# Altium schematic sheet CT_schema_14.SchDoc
size 278 x 170 mm
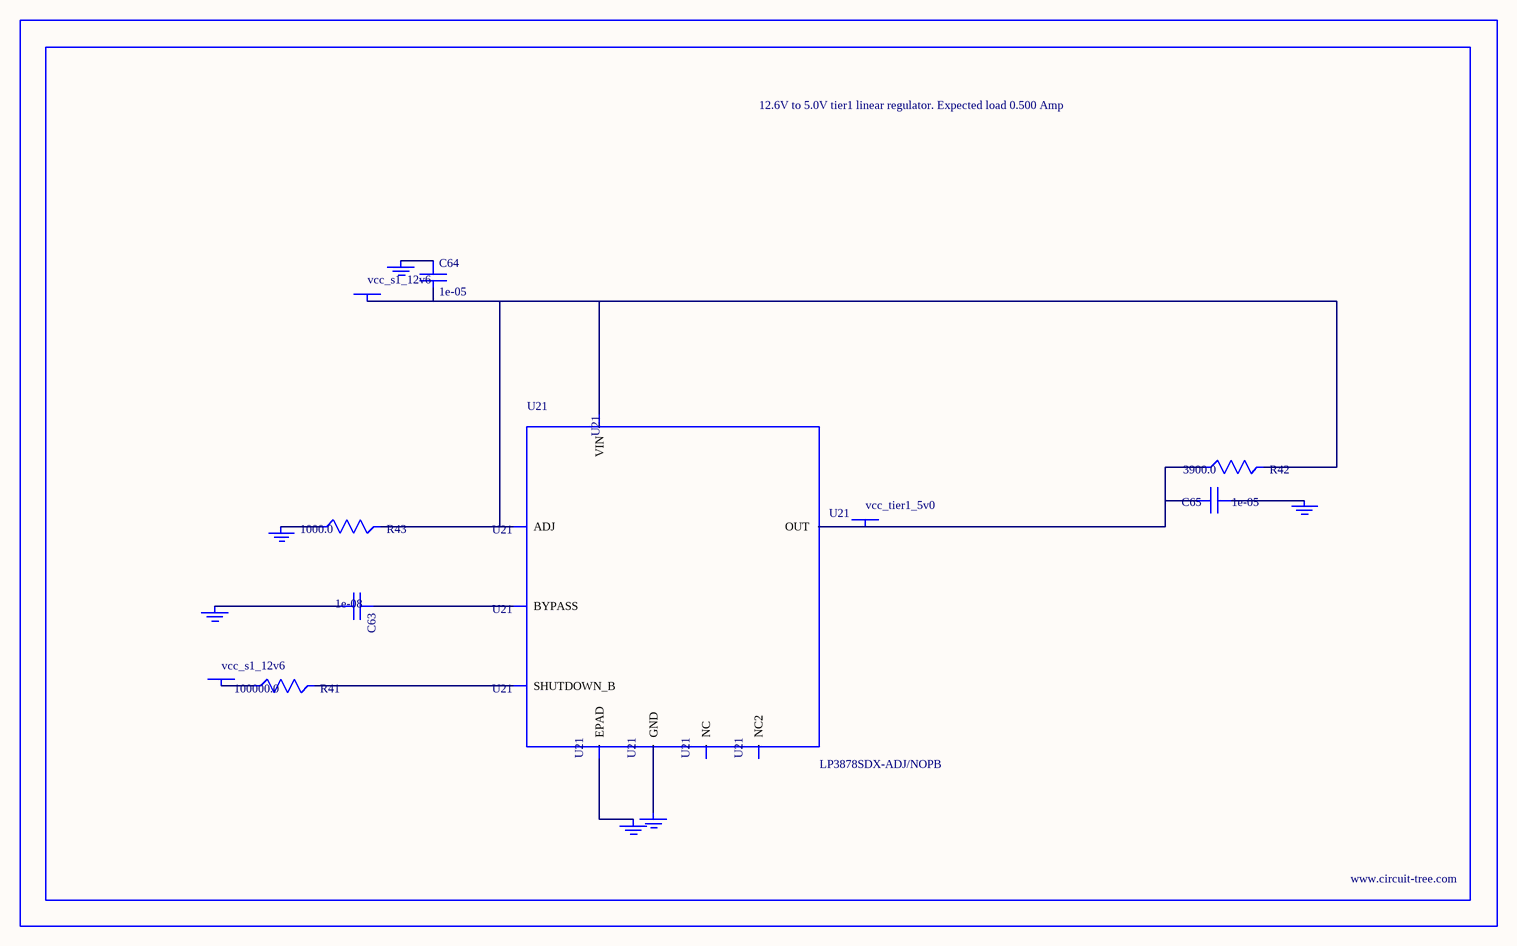
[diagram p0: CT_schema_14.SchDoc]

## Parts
BORDER13  (no value)
C63  1e-08  [C0402]
C64  1e-05  [C1210]
C65  1e-05  [C1210]
GND_INSTANCE_13_0  (no value)
GND_INSTANCE_13_1  (no value)
GND_INSTANCE_13_2  (no value)
GND_INSTANCE_13_3  (no value)
GND_INSTANCE_13_4  (no value)
GND_INSTANCE_13_5  (no value)
POWER_INSTANCE_13_0  vcc_s1_12v6
POWER_INSTANCE_13_1  vcc_s1_12v6
POWER_INSTANCE_13_2  vcc_tier1_5v0
R41  100000.0  [R0603]
R42  3900.0  [R0603]
R43  1000.0  [R0603]
U21  LP3878SDX-ADJ/NOPB  [WSON-8]

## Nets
NetC63_1: C63.1 U21.1(BYPASS)
NetC63_2: C63.2 GND_INSTANCE_13_0.0(GND)
NetC64_1: C64.1 GND_INSTANCE_13_1.0(GND)
NetC64_2: C64.2 POWER_INSTANCE_13_0.0(PWR) R42.2 R43.2 U21.4(VIN) U21.6(ADJ)
NetC65_1: C65.1 GND_INSTANCE_13_2.0(GND)
NetC65_2: C65.2 POWER_INSTANCE_13_2.0(PWR) R42.1 U21.5(OUT)
NetGND_INSTANCE_13_3_0: GND_INSTANCE_13_3.0(GND) R43.1
NetGND_INSTANCE_13_4_0: GND_INSTANCE_13_4.0(GND) U21.PAD(EPAD)
NetGND_INSTANCE_13_5_0: GND_INSTANCE_13_5.0(GND) U21.3(GND)
NetPOWER_INSTANCE_13_1_0: POWER_INSTANCE_13_1.0(PWR) R41.1
NetR41_2: R41.2 U21.8(SHUTDOWN_B)

Not connected (* = marked no-connect by the designer): U21 2(NC) 7(NC2)

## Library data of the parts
BORDER13 = BORDER_PAGE13
C63 = C0402C103K3RAC
C64 = C1210C106K5PACTU
C65 = GRM32DR61E106MA12L
GND_INSTANCE_13_0-GND_INSTANCE_13_5 = GND
POWER_INSTANCE_13_0-POWER_INSTANCE_13_2 = PWR
R41 = RC0603JR-07100KL
R42 = RC0603JR-073K9L
R43 = RC0603JR-071KL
